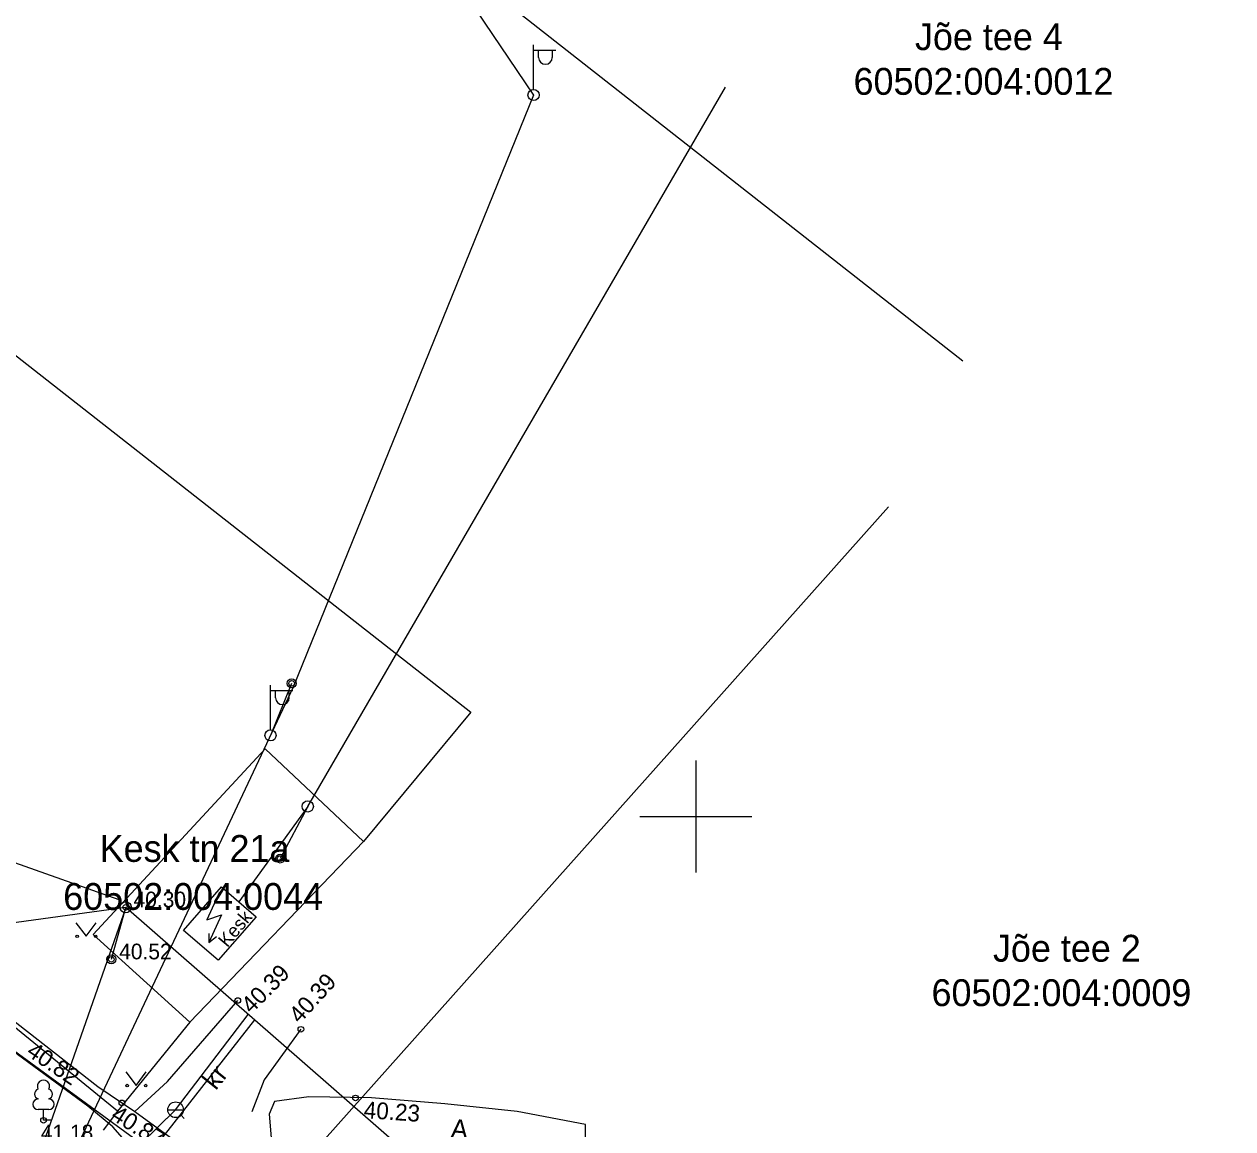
# Model space of a CAD drawing. Extents: x 641898 to 642452, y 6471715 to 6472255.
# Drawn here: x 642070 to 642124, y 6472036.1 to 6472085.4 of the extents above; entities that cross this region are included whole.
import ezdxf

# ---------------------------------------------------------------- set-up
doc = ezdxf.new("R2010")
doc.units = 0
for name, color, linetype in [('HALJASTUS', 7, 'Continuous'), ('HOONE', 7, 'Continuous'), ('KORGUS-EH2000', 7, 'Continuous'), ('KPOHULIIN', 7, 'Continuous'), ('KTRASS', 7, 'Continuous'), ('MPOHULIIN', 7, 'Continuous'), ('PIIR', 7, 'Continuous'), ('POST', 7, 'Continuous'), ('PUU', 7, 'Continuous'), ('TEE', 7, 'Continuous'), ('VKAEV', 7, 'Continuous'), ('VORK', 7, 'Continuous'), ('VTRASS', 7, 'Continuous')]:
    doc.layers.add(name, color=color, linetype=linetype)

msp = doc.modelspace()

# ---------------------------------------------------------------- linework, layer by layer
at = {"layer": 'HALJASTUS'}
for p, q in [((642072.32, 6472045.262), (642072.784, 6472044.655)), ((642072.784, 6472044.655), (642073.229, 6472045.262)), ((642074.552, 6472038.592), (642075.016, 6472037.986)), ((642075.016, 6472037.986), (642075.461, 6472038.592))]:
    msp.add_line(p, q, dxfattribs=at)
for centre in [(642072.383, 6472044.655), (642073.212, 6472044.655), (642074.615, 6472037.986), (642075.443, 6472037.986)]:
    msp.add_circle(centre, 0.055, dxfattribs=at)
at = {"layer": 'HOONE'}
for p, q in [((642078.744, 6472046.627), (642078.176, 6472045.385)), ((642078.176, 6472045.385), (642078.824, 6472045.61)), ((642078.824, 6472045.61), (642078.268, 6472044.381)), ((642078.268, 6472044.777), (642078.268, 6472044.381)), ((642078.268, 6472044.381), (642078.599, 6472044.645))]:
    msp.add_line(p, q, dxfattribs=at)
msp.add_lwpolyline([(642078.685, 6472043.58), (642077.138, 6472044.919), (642078.827, 6472046.859), (642080.374, 6472045.519), (642078.685, 6472043.58)], dxfattribs=at)
at = {"layer": 'KORGUS-EH2000'}
for centre in [(642081.958, 6472055.95), (642081.445, 6472048.127), (642074.552, 6472045.947), (642073.909, 6472043.625), (642079.555, 6472041.786), (642082.372, 6472040.499), (642074.38, 6472037.214), (642084.81, 6472037.432), (642070.879, 6472036.436)]:
    msp.add_circle(centre, 0.125, dxfattribs=at)
at = {"layer": 'KPOHULIIN'}
for q in [(642101.334, 6472082.588), (642079.601, 6472046.189)]:
    msp.add_line((642082.681, 6472050.453), q, dxfattribs=at)
at = {"layer": 'KTRASS'}
for points in [[(642074.26, 6472046.285), (642068.404, 6472048.354)], [(642075.289, 6472035.348), (642062.294, 6472044.84)], [(642080.297, 6472040.918), (642076.003, 6472035.433)]]:
    msp.add_lwpolyline(points, dxfattribs=at)
at = {"layer": 'MPOHULIIN'}
for points in [[(642026.721, 6472180.493), (642057.005, 6472135.15), (642092.759, 6472082.232), (642082.032, 6472055.789), (642066.817, 6472023.473)], [(642355.522, 6471813.313), (642331.534, 6471832.393), (642302.222, 6471855.921), (642271.629, 6471880.301), (642234.793, 6471909.555), (642198.436, 6471939.015), (642169.975, 6471961.956), (642133.076, 6471995.171), (642102.99, 6472021.089), (642074.552, 6472045.947), (642044.597, 6472041.824), (642019.939, 6472060.923), (641980.015, 6472091.706), (641945.513, 6472065.466), (641932.178, 6472056.628)], [(642074.552, 6472045.947), (642066.743, 6472023.634), (642053.137, 6472005.249)]]:
    msp.add_lwpolyline(points, dxfattribs=at)
at = {"layer": 'PIIR'}
for p, q in [((642016.19, 6472112.51), (642089.96, 6472054.66)), ((642111.934, 6472070.343), (642081.23, 6472094.44)), ((642074.19, 6472036.84), (642017.33, 6472083.13)), ((642083.42, 6472035.57), (642108.604, 6472063.83)), ((642089.96, 6472054.66), (642085.17, 6472048.89)), ((642073.09, 6472044.74), (642080.78, 6472053.03)), ((642080.78, 6472053.03), (642085.17, 6472048.89)), ((642085.17, 6472048.89), (642077.42, 6472040.82)), ((642077.42, 6472040.82), (642073.09, 6472044.74)), ((642077.42, 6472040.82), (642074.19, 6472036.84)), ((642074.19, 6472036.84), (642073.54, 6472035.99))]:
    msp.add_line(p, q, dxfattribs=at)
at = {"layer": 'POST'}
for p, q in [((642092.759, 6472082.482), (642092.759, 6472084.482)), ((642092.759, 6472084.232), (642093.759, 6472084.232)), ((642092.986, 6472083.911), (642092.986, 6472084.232)), ((642093.599, 6472083.911), (642093.599, 6472084.232)), ((642092.759, 6472082.232), (642092.759, 6472082.232)), ((642081.958, 6472055.95), (642081.015, 6472053.628)), ((642081.015, 6472053.878), (642081.015, 6472055.878)), ((642081.015, 6472055.628), (642082.015, 6472055.628)), ((642081.241, 6472055.307), (642081.241, 6472055.628)), ((642081.854, 6472055.307), (642081.854, 6472055.628)), ((642081.015, 6472053.628), (642081.015, 6472053.628)), ((642082.681, 6472050.453), (642081.445, 6472048.127)), ((642073.909, 6472043.625), (642074.552, 6472045.947))]:
    msp.add_line(p, q, dxfattribs=at)
for centre, radius in [((642092.759, 6472082.232), 0.25), ((642081.958, 6472055.95), 0.2), ((642081.015, 6472053.628), 0.25), ((642082.681, 6472050.453), 0.25), ((642081.445, 6472048.127), 0.2), ((642074.552, 6472045.947), 0.25), ((642073.909, 6472043.625), 0.2)]:
    msp.add_circle(centre, radius, dxfattribs=at)
for centre in [(642093.292, 6472083.911), (642081.548, 6472055.307)]:
    msp.add_arc(centre, 0.306, 180, 0, dxfattribs=at)
at = {"layer": 'PUU'}
for p, q in [((642071.119, 6472036.911), (642070.639, 6472036.911)), ((642070.879, 6472036.436), (642070.879, 6472036.911)), ((642071.259, 6472036.436), (642070.879, 6472036.436))]:
    msp.add_line(p, q, dxfattribs=at)
for centre, radius, start, end in [((642070.709, 6472037.609), 0.233, 109.0217, 253.1415), ((642070.879, 6472037.956), 0.277, 332.5799, 207.4201), ((642071.049, 6472037.609), 0.233, 286.8508, 70.9859), ((642070.642, 6472037.148), 0.238, 90.0016, 269.3953), ((642071.116, 6472037.148), 0.238, 270.6047, 89.9984)]:
    msp.add_arc(centre, radius, start, end, dxfattribs=at)
at = {"layer": 'TEE'}
for points in [[(642074.504, 6472035.529), (642073.973, 6472036.136), (642072.852, 6472037.067), (642069.722, 6472039.369), (642062.895, 6472044.891), (642057.209, 6472049.515), (642057.815, 6472050.19), (642064.692, 6472044.68), (642073.313, 6472037.937), (642074.955, 6472036.833), (642077.148, 6472035.23)], [(642074.955, 6472036.833), (642076.411, 6472038.173), (642079.555, 6472041.786)], [(642082.372, 6472040.499), (642080.733, 6472038.238), (642080.175, 6472036.806)], [(642094.797, 6472033.371), (642095.075, 6472034.807), (642095.084, 6472036.251), (642092.031, 6472036.822), (642088.805, 6472037.164), (642085.522, 6472037.434), (642082.733, 6472037.479), (642081.2, 6472037.267), (642080.962, 6472036.705), (642081.071, 6472035.3), (642080.641, 6472035.163), (642080.76, 6472034.485), (642082.923, 6472034.581), (642085.466, 6472034.656), (642088.646, 6472034.451), (642091.703, 6472033.998), (642093.846, 6472033.603), (642094.797, 6472033.371)]]:
    msp.add_lwpolyline(points, dxfattribs=at)
at = {"layer": 'VKAEV'}
for p, q in [((642076.533, 6472036.657), (642076.393, 6472036.517)), ((642076.43, 6472036.904), (642077.13, 6472036.904)), ((642077.027, 6472036.657), (642077.167, 6472036.517))]:
    msp.add_line(p, q, dxfattribs=at)
msp.add_circle((642076.78, 6472036.904), 0.35, dxfattribs=at)
at = {"layer": 'VORK'}
for p, q in [((642100, 6472052.5), (642100, 6472047.5)), ((642097.5, 6472050), (642102.5, 6472050))]:
    msp.add_line(p, q, dxfattribs=at)
at = {"layer": 'VTRASS'}
msp.add_lwpolyline([(642070.54, 6472026.319), (642075.225, 6472035.385), (642076.78, 6472036.904), (642080.024, 6472041.161)], dxfattribs=at)

# ---------------------------------------------------------------- texts
at = {"layer": 'HOONE'}
msp.add_text('Kesk', height=0.6, rotation=49.8582, dxfattribs=at).set_placement((642079.085, 6472044.124))
at = {"layer": 'KORGUS-EH2000'}
for s, p in [('40.30', (642074.902, 6472045.947)), ('40.52', (642074.259, 6472043.625)), ('41.18', (642070.759, 6472035.538))]:
    msp.add_text(s, height=0.7, dxfattribs=at).set_placement(p)
for s, rotation, p in [('40.39', 45.2473, (642080.162, 6472041.159)), ('40.39', 47.7434, (642082.319, 6472040.717)), ('40.82', 325.8095, (642070.072, 6472039.369)), ('40.23', 356.0687, (642085.16, 6472036.537)), ('40.87', 328.1278, (642073.841, 6472036.509))]:
    msp.add_text(s, height=0.75, rotation=rotation, dxfattribs=at).set_placement(p)
at = {"layer": 'PIIR'}
for s, p in [('Jõe tee 4', (642109.79, 6472084.238)), ('60502:004:0012', (642107.047, 6472082.243)), ('Kesk tn 21a', (642073.387, 6472047.977)), ('60502:004:0044', (642071.759, 6472045.832)), ('Jõe tee 2', (642113.272, 6472043.519)), ('60502:004:0009', (642110.529, 6472041.535))]:
    msp.add_text(s, height=1.2, dxfattribs=at).set_placement(p)
at = {"layer": 'TEE'}
for s, rotation, p in [('kr', 51.3402, (642078.571, 6472037.741)), ('A', 355.1642, (642089.044, 6472035.655))]:
    msp.add_text(s, height=0.85, rotation=rotation, dxfattribs=at).set_placement(p)

doc.saveas('drawing.dxf')
